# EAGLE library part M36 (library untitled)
Centronics-Stecker
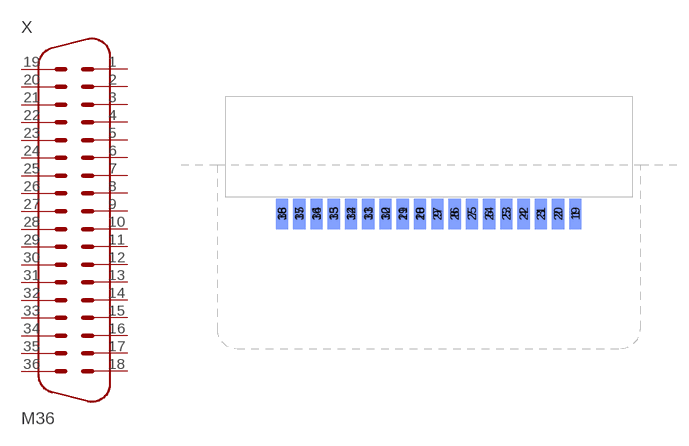
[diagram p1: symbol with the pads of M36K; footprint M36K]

Designator prefix X

## M36K  [M36K]
1  1
2  2
3  3
4  4
5  5
6  6
7  7
8  8
9  9
10  10
11  11
12  12
13  13
14  14
15  15
16  16
17  17
18  18
19  19
20  20
21  21
22  22
23  23
24  24
25  25
26  26
27  27
28  28
29  29
30  30
31  31
32  32
33  33
34  34
35  35
36  36

## Footprint M36K (pad centres in mm)
Centronics-Stecker 36pol Kantenmontage, Pins zusammenbiegen! Pin-Raster: 85 mil Gestrichelte Linie: Gehäuse (außen), ohne Zugentlastung Reichelt: SE5736M 0,87&euro;
smd 1.524 x 3.81: 1 18.352,-2.159; 2 16.192,-2.159; 3 14.034,-2.159; 4 11.874,-2.159; 5 9.716,-2.159; 6 7.556,-2.159; 7 5.397,-2.159; 8 3.239,-2.159; 9 1.079,-2.159; 10 -1.079,-2.159; 11 -3.239,-2.159; 12 -5.397,-2.159; 13 -7.556,-2.159; 14 -9.716,-2.159; 15 -11.874,-2.159; 16 -14.034,-2.159; 17 -16.192,-2.159; 18 -18.352,-2.159
smd 1.524 x 3.81 bottom: 19 18.352,-2.159; 20 16.192,-2.159; 21 14.034,-2.159; 22 11.874,-2.159; 23 9.716,-2.159; 24 7.556,-2.159; 25 5.397,-2.159; 26 3.239,-2.159; 27 1.079,-2.159; 28 -1.079,-2.159; 29 -3.239,-2.159; 30 -5.397,-2.159; 31 -7.556,-2.159; 32 -9.716,-2.159; 33 -11.874,-2.159; 34 -14.034,-2.159; 35 -16.192,-2.159; 36 -18.352,-2.159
